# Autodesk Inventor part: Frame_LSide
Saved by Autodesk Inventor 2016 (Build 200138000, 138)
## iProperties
Created: 2015-11
Part Number: Frame_LSide
Material: Generic
Document SubType Name: Modeling
Designer: John
Density: 1 g/cm^3
Appearance: Default
Author: John
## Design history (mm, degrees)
feature "SOLID1"
body "Solid1"
